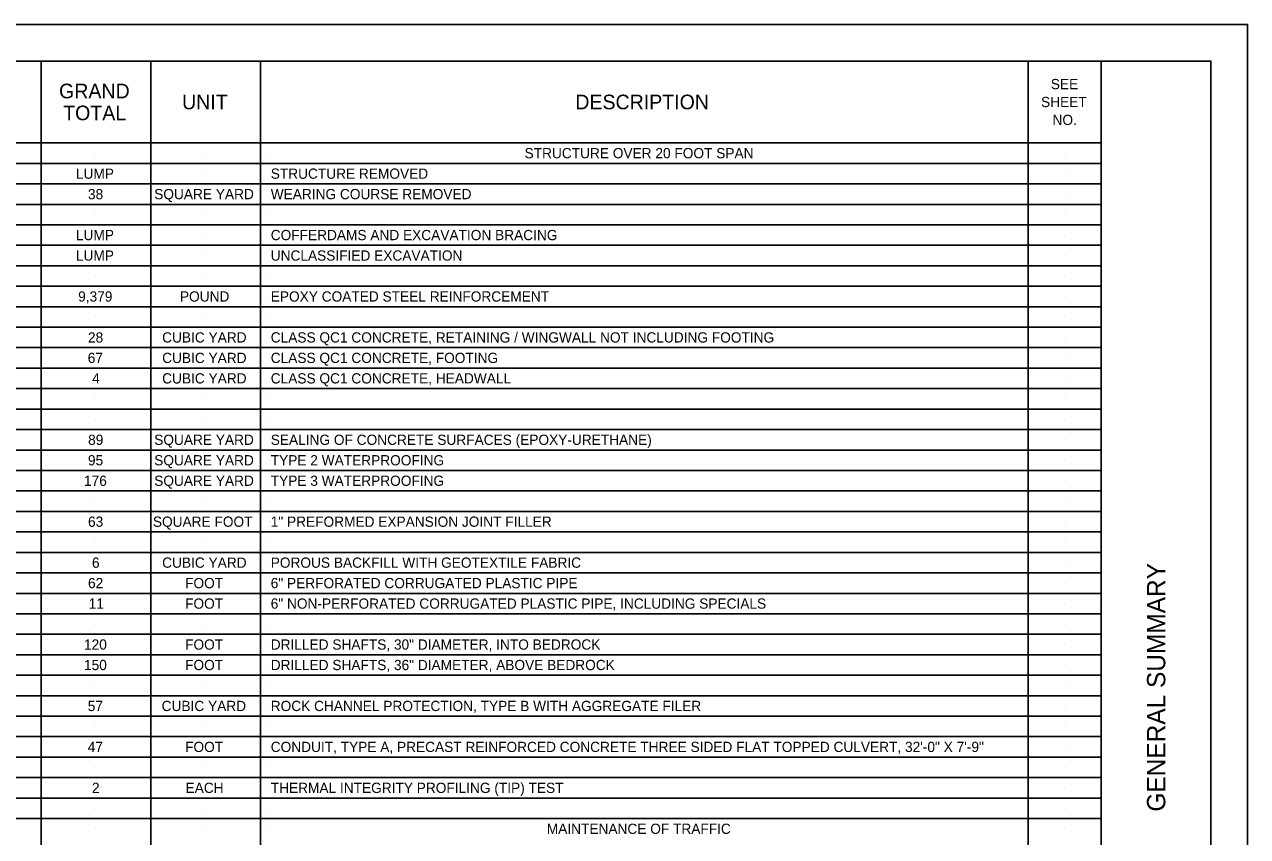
# Model space of a CAD drawing. Extents: x 0 to 34, y 0 to 22.
# Drawn here: x 17.27 to 34, y 10.89 to 22 of the extents above; entities that cross this region are included whole.
import ezdxf

# ---------------------------------------------------------------- set-up
doc = ezdxf.new("R2010")
doc.units = 0
for name, color, linetype in [('RD_P_Text', 7, 'Continuous'), ('SC_Scratch1', 7, 'Continuous'), ('SH_Border', 7, 'Continuous'), ('SH_Cut_Line', 7, 'Continuous'), ('SH_Data', 7, 'Continuous')]:
    doc.layers.add(name, color=color, linetype=linetype)

msp = doc.modelspace()

# ---------------------------------------------------------------- linework, layer by layer
at = {"layer": 'SC_Scratch1'}
for p, q in [((18.25, 20.24), (18.25, 20.24)), ((19.75, 20.24), (19.75, 20.24)), ((20.64, 20.24), (20.64, 20.24)), ((31.5, 20.24), (31.5, 20.24)), ((18.25, 19.96), (18.25, 19.96)), ((19.75, 19.96), (19.75, 19.96)), ((20.64, 19.96), (20.64, 19.96)), ((31.5, 19.96), (31.5, 19.96)), ((18.25, 19.68), (18.25, 19.68)), ((19.75, 19.68), (19.75, 19.68)), ((20.64, 19.68), (20.64, 19.68)), ((31.5, 19.68), (31.5, 19.68)), ((18.25, 19.4), (18.25, 19.4)), ((19.75, 19.4), (19.75, 19.4)), ((20.64, 19.4), (20.64, 19.4)), ((31.5, 19.4), (31.5, 19.4)), ((18.25, 19.12), (18.25, 19.12)), ((19.75, 19.12), (19.75, 19.12)), ((20.64, 19.12), (20.64, 19.12)), ((31.5, 19.12), (31.5, 19.12)), ((18.25, 18.84), (18.25, 18.84)), ((19.75, 18.84), (19.75, 18.84)), ((20.64, 18.84), (20.64, 18.84)), ((31.5, 18.84), (31.5, 18.84)), ((18.25, 18.56), (18.25, 18.56)), ((19.75, 18.56), (19.75, 18.56)), ((20.64, 18.56), (20.64, 18.56)), ((31.5, 18.56), (31.5, 18.56)), ((18.25, 18.28), (18.25, 18.28)), ((19.75, 18.28), (19.75, 18.28)), ((20.64, 18.28), (20.64, 18.28)), ((31.5, 18.28), (31.5, 18.28)), ((18.25, 18), (18.25, 18)), ((19.75, 18), (19.75, 18)), ((20.64, 18), (20.64, 18)), ((31.5, 18), (31.5, 18)), ((18.25, 17.72), (18.25, 17.72)), ((19.75, 17.72), (19.75, 17.72)), ((20.64, 17.72), (20.64, 17.72)), ((31.5, 17.72), (31.5, 17.72)), ((18.25, 17.44), (18.25, 17.44)), ((19.75, 17.44), (19.75, 17.44)), ((20.64, 17.44), (20.64, 17.44)), ((31.5, 17.44), (31.5, 17.44)), ((18.25, 17.16), (18.25, 17.16)), ((19.75, 17.16), (19.75, 17.16)), ((20.64, 17.16), (20.64, 17.16)), ((31.5, 17.16), (31.5, 17.16)), ((18.25, 16.88), (18.25, 16.88)), ((19.75, 16.88), (19.75, 16.88)), ((20.64, 16.88), (20.64, 16.88)), ((31.5, 16.88), (31.5, 16.88)), ((18.25, 16.6), (18.25, 16.6)), ((19.75, 16.6), (19.75, 16.6)), ((20.64, 16.6), (20.64, 16.6)), ((31.5, 16.6), (31.5, 16.6)), ((18.25, 16.32), (18.25, 16.32)), ((19.75, 16.32), (19.75, 16.32)), ((20.64, 16.32), (20.64, 16.32)), ((31.5, 16.32), (31.5, 16.32)), ((18.25, 16.04), (18.25, 16.04)), ((19.75, 16.04), (19.75, 16.04)), ((20.64, 16.04), (20.64, 16.04)), ((31.5, 16.04), (31.5, 16.04)), ((18.25, 15.76), (18.25, 15.76)), ((19.75, 15.76), (19.75, 15.76)), ((20.64, 15.76), (20.64, 15.76)), ((31.5, 15.76), (31.5, 15.76)), ((18.25, 15.48), (18.25, 15.48)), ((19.75, 15.48), (19.75, 15.48)), ((20.64, 15.48), (20.64, 15.48)), ((31.5, 15.48), (31.5, 15.48)), ((18.25, 15.2), (18.25, 15.2)), ((19.75, 15.2), (19.75, 15.2)), ((20.64, 15.2), (20.64, 15.2)), ((31.5, 15.2), (31.5, 15.2)), ((18.25, 14.92), (18.25, 14.92)), ((19.75, 14.92), (19.75, 14.92)), ((20.64, 14.92), (20.64, 14.92)), ((31.5, 14.92), (31.5, 14.92)), ((18.25, 14.64), (18.25, 14.64)), ((19.75, 14.64), (19.75, 14.64)), ((20.64, 14.64), (20.64, 14.64)), ((31.5, 14.64), (31.5, 14.64)), ((18.25, 14.36), (18.25, 14.36)), ((19.75, 14.36), (19.75, 14.36)), ((20.64, 14.36), (20.64, 14.36)), ((31.5, 14.36), (31.5, 14.36)), ((18.25, 14.08), (18.25, 14.08)), ((19.75, 14.08), (19.75, 14.08)), ((20.64, 14.08), (20.64, 14.08)), ((31.5, 14.08), (31.5, 14.08)), ((18.25, 13.8), (18.25, 13.8)), ((19.75, 13.8), (19.75, 13.8)), ((20.64, 13.8), (20.64, 13.8)), ((31.5, 13.8), (31.5, 13.8)), ((18.25, 13.52), (18.25, 13.52)), ((19.75, 13.52), (19.75, 13.52)), ((20.64, 13.52), (20.64, 13.52)), ((31.5, 13.52), (31.5, 13.52)), ((18.25, 13.24), (18.25, 13.24)), ((19.75, 13.24), (19.75, 13.24)), ((20.64, 13.24), (20.64, 13.24)), ((31.5, 13.24), (31.5, 13.24)), ((18.25, 12.96), (18.25, 12.96)), ((19.75, 12.96), (19.75, 12.96)), ((20.64, 12.96), (20.64, 12.96)), ((31.5, 12.96), (31.5, 12.96)), ((18.25, 12.68), (18.25, 12.68)), ((19.75, 12.68), (19.75, 12.68)), ((20.64, 12.68), (20.64, 12.68)), ((31.5, 12.68), (31.5, 12.68)), ((18.25, 12.4), (18.25, 12.4)), ((19.75, 12.4), (19.75, 12.4)), ((20.64, 12.4), (20.64, 12.4)), ((31.5, 12.4), (31.5, 12.4)), ((18.25, 12.12), (18.25, 12.12)), ((19.75, 12.12), (19.75, 12.12)), ((20.64, 12.12), (20.64, 12.12)), ((31.5, 12.12), (31.5, 12.12)), ((18.25, 11.84), (18.25, 11.84)), ((19.75, 11.84), (19.75, 11.84)), ((20.64, 11.84), (20.64, 11.84)), ((31.5, 11.84), (31.5, 11.84)), ((18.25, 11.56), (18.25, 11.56)), ((19.75, 11.56), (19.75, 11.56)), ((20.64, 11.56), (20.64, 11.56)), ((31.5, 11.56), (31.5, 11.56)), ((18.25, 11.28), (18.25, 11.28)), ((19.75, 11.28), (19.75, 11.28)), ((20.64, 11.28), (20.64, 11.28)), ((31.5, 11.28), (31.5, 11.28)), ((18.25, 11), (18.25, 11)), ((19.75, 11), (19.75, 11)), ((20.64, 11), (20.64, 11)), ((31.5, 11), (31.5, 11))]:
    msp.add_line(p, q, dxfattribs=at)
at = {"layer": 'SH_Border'}
msp.add_line((32, 0.5), (32, 21.5), dxfattribs=at)
msp.add_lwpolyline([(1.5, 21.5), (33.5, 21.5), (33.5, 0.5), (1.5, 0.5)], close=True, dxfattribs=at)
at = {"layer": 'SH_Cut_Line'}
msp.add_lwpolyline([(0, 0), (34, 0), (34, 22), (0, 22)], close=True, dxfattribs=at)
at = {"layer": 'SH_Data'}
for p, q in [((17.5, 21.5), (17.5, 0.5)), ((19, 21.5), (19, 0.5)), ((20.5, 21.5), (20.5, 0.5)), ((31, 21.5), (31, 0.5)), ((32, 20.38), (1.5, 20.38)), ((32, 20.1), (1.5, 20.1)), ((32, 19.82), (1.5, 19.82)), ((32, 19.54), (1.5, 19.54)), ((32, 19.26), (1.5, 19.26)), ((32, 18.98), (1.5, 18.98)), ((32, 18.7), (1.5, 18.7)), ((32, 18.42), (1.5, 18.42)), ((32, 18.14), (1.5, 18.14)), ((32, 17.86), (1.5, 17.86)), ((32, 17.58), (1.5, 17.58)), ((32, 17.3), (1.5, 17.3)), ((32, 17.02), (1.5, 17.02)), ((32, 16.74), (1.5, 16.74)), ((32, 16.46), (1.5, 16.46)), ((32, 16.18), (1.5, 16.18)), ((32, 15.9), (1.5, 15.9)), ((32, 15.62), (1.5, 15.62)), ((32, 15.34), (1.5, 15.34)), ((32, 15.06), (1.5, 15.06)), ((32, 14.78), (1.5, 14.78)), ((32, 14.5), (1.5, 14.5)), ((32, 14.22), (1.5, 14.22)), ((32, 13.94), (1.5, 13.94)), ((32, 13.66), (1.5, 13.66)), ((32, 13.38), (1.5, 13.38)), ((32, 13.1), (1.5, 13.1)), ((32, 12.82), (1.5, 12.82)), ((32, 12.54), (1.5, 12.54)), ((32, 12.26), (1.5, 12.26)), ((32, 11.98), (1.5, 11.98)), ((32, 11.7), (1.5, 11.7)), ((32, 11.42), (1.5, 11.42)), ((32, 11.14), (1.5, 11.14))]:
    msp.add_line(p, q, dxfattribs=at)

# ---------------------------------------------------------------- texts
at = {"layer": 'RD_P_Text'}
for s, p in [('STRUCTURE OVER 20 FOOT SPAN', (24.112, 20.17)), ('LUMP', (17.975, 19.89)), ('STRUCTURE REMOVED', (20.64, 19.89)), ('38', (18.14, 19.61)), ('SQUARE YARD', (19.046, 19.61)), ('WEARING COURSE REMOVED', (20.64, 19.61)), ('LUMP', (17.975, 19.05)), ('COFFERDAMS AND EXCAVATION BRACING', (20.64, 19.05)), ('LUMP', (17.975, 18.77)), ('UNCLASSIFIED EXCAVATION', (20.64, 18.77)), ('9,379', (18.006, 18.21)), ('POUND', (19.398, 18.21)), ('EPOXY COATED STEEL REINFORCEMENT', (20.64, 18.21)), ('28', (18.14, 17.65)), ('CUBIC YARD', (19.155, 17.65)), ('CLASS QC1 CONCRETE, RETAINING / WINGWALL NOT INCLUDING FOOTING', (20.64, 17.65)), ('67', (18.137, 17.37)), ('CUBIC YARD', (19.155, 17.37)), ('CLASS QC1 CONCRETE, FOOTING', (20.64, 17.37)), ('CUBIC YARD', (19.155, 17.09)), ('CLASS QC1 CONCRETE, HEADWALL', (20.64, 17.09)), ('4', (18.197, 17.09)), ('SEALING OF CONCRETE SURFACES (EPOXY-URETHANE)', (20.64, 16.25)), ('89', (18.142, 16.25)), ('SQUARE YARD', (19.046, 16.25)), ('95', (18.14, 15.97)), ('SQUARE YARD', (19.046, 15.97)), ('TYPE 2 WATERPROOFING', (20.64, 15.97)), ('176', (18.086, 15.69)), ('SQUARE YARD', (19.046, 15.69)), ('TYPE 3 WATERPROOFING', (20.64, 15.69)), ('63', (18.141, 15.13)), ('SQUARE FOOT', (19.028, 15.13)), ('1" PREFORMED EXPANSION JOINT FILLER', (20.64, 15.13)), ('6', (18.195, 14.57)), ('CUBIC YARD', (19.155, 14.57)), ('POROUS BACKFILL WITH GEOTEXTILE FABRIC', (20.64, 14.57)), ('62', (18.141, 14.29)), ('FOOT', (19.469, 14.29)), ('6" PERFORATED CORRUGATED PLASTIC PIPE', (20.64, 14.29)), ('11', (18.149, 14.01)), ('FOOT', (19.469, 14.01)), ('6" NON-PERFORATED CORRUGATED PLASTIC PIPE, INCLUDING SPECIALS', (20.64, 14.01)), ('120', (18.086, 13.45)), ('FOOT', (19.469, 13.45)), ('DRILLED SHAFTS, 30" DIAMETER, INTO BEDROCK', (20.64, 13.45)), ('150', (18.086, 13.17)), ('FOOT', (19.469, 13.17)), ('DRILLED SHAFTS, 36" DIAMETER, ABOVE BEDROCK', (20.64, 13.17)), ('57', (18.137, 12.61)), ('CUBIC YARD', (19.148, 12.61)), ('ROCK CHANNEL PROTECTION, TYPE B WITH AGGREGATE FILER', (20.64, 12.61)), ('47', (18.137, 12.05)), ('FOOT', (19.469, 12.05)), ('CONDUIT, TYPE A, PRECAST REINFORCED CONCRETE THREE SIDED FLAT TOPPED CULVERT, 32\'-0" X 7\'-9"', (20.64, 12.05)), ('2', (18.195, 11.49)), ('EACH', (19.475, 11.49)), ('THERMAL INTEGRITY PROFILING (TIP) TEST', (20.64, 11.49)), ('MAINTENANCE OF TRAFFIC', (24.416, 10.93))]:
    msp.add_text(s, height=0.14, dxfattribs=at).set_placement(p)
at = {"layer": 'SH_Data'}
for s, height, p in [('SEE', 0.14, (31.309, 21.115)), ('GRAND', 0.2, (17.745, 20.99)), ('UNIT', 0.2, (19.427, 20.84)), ('DESCRIPTION', 0.2, (24.806, 20.84)), ('SHEET', 0.14, (31.176, 20.87)), ('TOTAL', 0.2, (17.801, 20.69)), ('NO.', 0.14, (31.333, 20.625))]:
    msp.add_text(s, height=height, dxfattribs=at).set_placement(p)
msp.add_text('GENERAL SUMMARY', height=0.25, rotation=90, dxfattribs=at).set_placement((32.875, 11.235))

doc.saveas('drawing.dxf')
